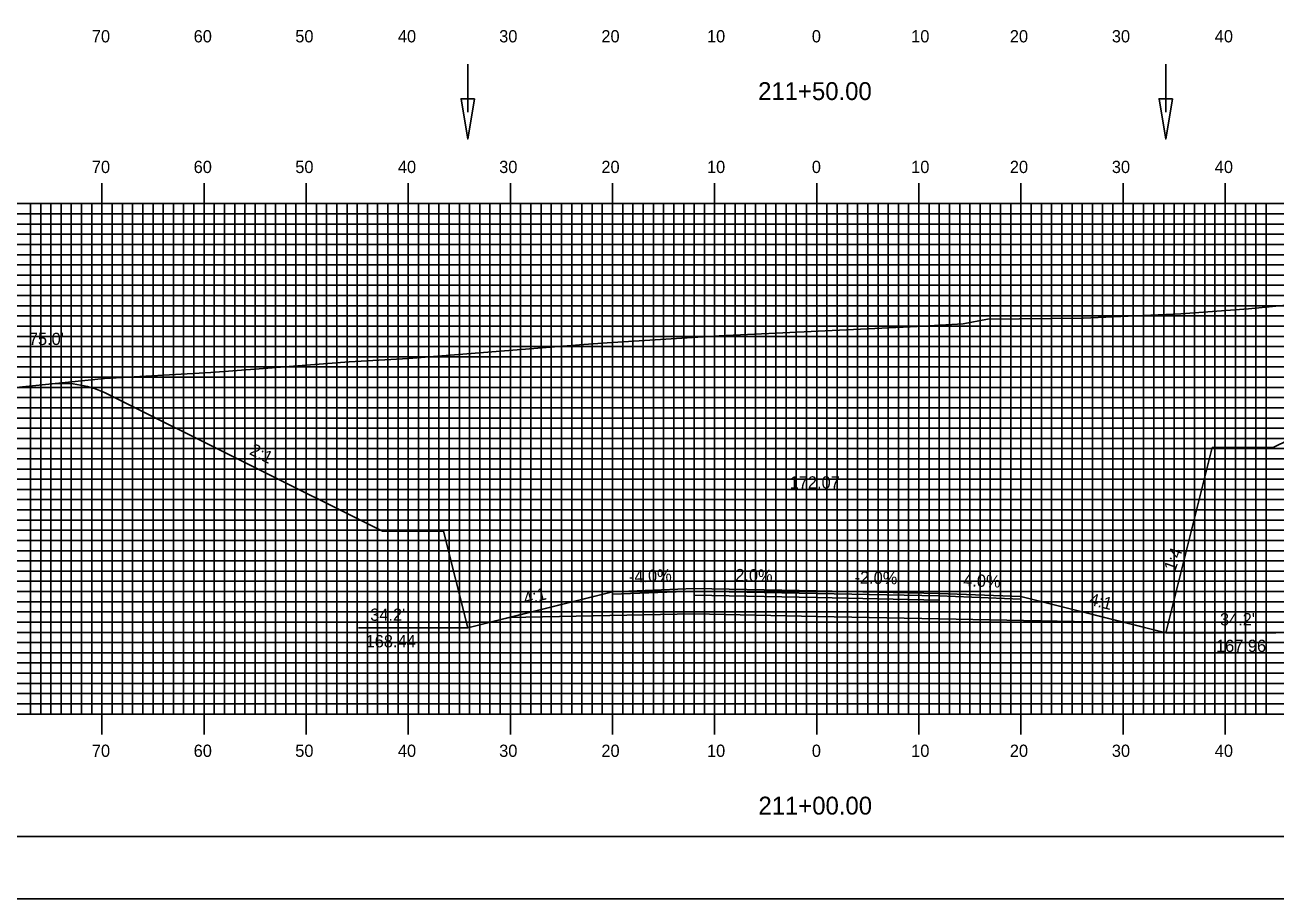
# Model space of a CAD drawing. Extents: x 1794846 to 1795189, y 442591 to 442811.
# Drawn here: x 1794934.3 to 1795056.8, y 442590.5 to 442676.2 of the extents above; entities that cross this region are included whole.
import ezdxf

# ---------------------------------------------------------------- set-up
doc = ezdxf.new("R2010")
doc.units = 0
for name, color, linetype in [('ANNOTATION', 7, 'Continuous'), ('BORDER', 7, 'Continuous'), ('D_Drainage_Ditch_Line', 7, 'Continuous'), ('D_Roadway_Centerline', 7, 'Continuous'), ('D_Roadway_Centerline_Text', 7, 'Continuous'), ('D_Roadway_Edge_Shoulder', 7, 'Continuous'), ('D_Roadway_Edge_TW', 7, 'Continuous'), ('D_Roadway_FinishedGrade', 7, 'Continuous'), ('D_Roadway_Pavement', 7, 'Continuous'), ('D_Roadway_SlopeLines', 7, 'Continuous'), ('D_Roadway_SubGrade', 7, 'Continuous'), ('D_Text_Standard', 7, 'Continuous'), ('H_V ANNOTATION', 7, 'Continuous'), ('MAJOR', 7, 'Continuous'), ('MINOR', 7, 'Continuous'), ('PDRAIN', 7, 'Continuous'), ('PLOT BOUNDARY', 7, 'Continuous'), ('S_Roadway_Centerline', 7, 'Continuous')]:
    doc.layers.add(name, color=color, linetype=linetype)

msp = doc.modelspace()

# ---------------------------------------------------------------- linework, layer by layer
at = {"layer": 'BORDER'}
msp.add_lwpolyline([(1794862.25, 442596.67), (1795182.25, 442596.67), (1795182.25, 442806.67), (1794862.25, 442806.67)], close=True, dxfattribs=at)
at = {"layer": 'D_Drainage_Ditch_Line'}
for p, q in [((1794977.68, 442667.63), (1794977.68, 442672.33)), ((1795046.03, 442667.63), (1795046.03, 442672.33))]:
    msp.add_line(p, q, dxfattribs=at)
for points in [[(1794978.34, 442668.94), (1794977.02, 442668.94), (1794977.68, 442665)], [(1795046.68, 442668.94), (1795045.37, 442668.94), (1795046.03, 442665)]]:
    msp.add_lwpolyline(points, close=True, dxfattribs=at)
at = {"layer": 'D_Roadway_Centerline'}
msp.add_lwpolyline([(1794977.68, 442617.11), (1794981.68, 442618.11), (1794991.85, 442620.65), (1794999.85, 442620.97), (1795011.85, 442620.73), (1795023.85, 442620.49), (1795031.85, 442620.17), (1795042.03, 442617.63), (1795046.03, 442616.63)], dxfattribs=at)
at = {"layer": 'D_Roadway_Edge_Shoulder'}
for points in [[(1794999.85, 442620.97), (1794991.85, 442620.65), (1794991.85, 442620.4), (1794999.85, 442620.72)], [(1795023.85, 442620.49), (1795031.85, 442620.17), (1795031.85, 442619.92), (1795023.85, 442620.24)]]:
    msp.add_lwpolyline(points, close=True, dxfattribs=at)
at = {"layer": 'D_Roadway_Edge_TW'}
msp.add_lwpolyline([(1794999.85, 442620.72), (1794999.85, 442620.97), (1795011.85, 442620.73), (1795023.85, 442620.49), (1795023.85, 442620.24), (1795011.85, 442620.48)], close=True, dxfattribs=at)
at = {"layer": 'D_Roadway_FinishedGrade'}
msp.add_arc((1794937.96, 442631.06), 10, 63.4349, 96.0931, dxfattribs=at)
at = {"layer": 'D_Roadway_Pavement'}
msp.add_lwpolyline([(1794999.85, 442620.31), (1794999.85, 442620.72), (1795011.85, 442620.48), (1795023.85, 442620.24), (1795023.85, 442619.83), (1795011.85, 442620.07)], close=True, dxfattribs=at)
at = {"layer": 'D_Roadway_SlopeLines'}
for p, q in [((1795056.56, 442634.77), (1795080.92, 442646.94)), ((1795046.03, 442616.63), (1795050.56, 442634.77)), ((1795050.56, 442634.77), (1795056.56, 442634.77)), ((1794977.68, 442617.11), (1794975.31, 442626.57))]:
    msp.add_line(p, q, dxfattribs=at)
for points in [[(1794975.31, 442626.57), (1794969.31, 442626.57), (1794942.43, 442640.01)], [(1794991.85, 442620.65), (1794977.68, 442617.11)], [(1795031.85, 442620.17), (1795046.03, 442616.63)]]:
    msp.add_lwpolyline(points, dxfattribs=at)
at = {"layer": 'D_Roadway_SubGrade'}
msp.add_lwpolyline([(1794999.85, 442618.47), (1794981.68, 442618.11), (1794991.85, 442620.65), (1794991.85, 442620.4), (1794999.85, 442620.72), (1795011.85, 442620.48), (1795023.85, 442620.24), (1795031.85, 442619.92), (1795031.85, 442620.17), (1795042.03, 442617.63), (1795023.85, 442617.99), (1795011.85, 442618.23)], close=True, dxfattribs=at)
at = {"layer": 'MAJOR'}
for p, q in [((1794941.85, 442660.67), (1794941.85, 442658.67)), ((1794951.85, 442660.67), (1794951.85, 442658.67)), ((1794961.85, 442660.67), (1794961.85, 442658.67)), ((1794971.85, 442660.67), (1794971.85, 442658.67)), ((1794981.85, 442660.67), (1794981.85, 442658.67)), ((1794991.85, 442660.67), (1794991.85, 442658.67)), ((1795001.85, 442660.67), (1795001.85, 442658.67)), ((1795011.85, 442660.67), (1795011.85, 442658.67)), ((1795021.85, 442660.67), (1795021.85, 442658.67)), ((1795031.85, 442660.67), (1795031.85, 442658.67)), ((1795041.85, 442660.67), (1795041.85, 442658.67)), ((1795051.85, 442660.67), (1795051.85, 442658.67)), ((1794871.85, 442658.67), (1795151.85, 442658.67)), ((1794871.85, 442658.67), (1795151.85, 442658.67)), ((1794941.85, 442608.67), (1794941.85, 442658.67)), ((1794951.85, 442608.67), (1794951.85, 442658.67)), ((1794961.85, 442608.67), (1794961.85, 442658.67)), ((1794971.85, 442608.67), (1794971.85, 442658.67)), ((1794981.85, 442608.67), (1794981.85, 442658.67)), ((1794991.85, 442608.67), (1794991.85, 442658.67)), ((1795001.85, 442608.67), (1795001.85, 442658.67)), ((1795011.85, 442608.67), (1795011.85, 442658.67)), ((1795021.85, 442608.67), (1795021.85, 442658.67)), ((1795031.85, 442608.67), (1795031.85, 442658.67)), ((1795041.85, 442608.67), (1795041.85, 442658.67)), ((1795051.85, 442608.67), (1795051.85, 442658.67)), ((1794871.85, 442653.67), (1795151.85, 442653.67)), ((1794871.85, 442648.67), (1795151.85, 442648.67)), ((1794871.85, 442643.67), (1795151.85, 442643.67)), ((1794871.85, 442638.67), (1795151.85, 442638.67)), ((1794871.85, 442633.67), (1795151.85, 442633.67)), ((1794871.85, 442628.67), (1795151.85, 442628.67)), ((1794871.85, 442623.67), (1795151.85, 442623.67)), ((1794871.85, 442618.67), (1795151.85, 442618.67)), ((1794871.85, 442613.67), (1795151.85, 442613.67)), ((1794871.85, 442608.67), (1795151.85, 442608.67)), ((1794871.85, 442608.67), (1795151.85, 442608.67)), ((1794941.85, 442606.66), (1794941.85, 442608.67)), ((1794951.85, 442606.66), (1794951.85, 442608.67)), ((1794961.85, 442606.66), (1794961.85, 442608.67)), ((1794971.85, 442606.66), (1794971.85, 442608.67)), ((1794981.85, 442606.66), (1794981.85, 442608.67)), ((1794991.85, 442606.66), (1794991.85, 442608.67)), ((1795001.85, 442606.66), (1795001.85, 442608.67)), ((1795011.85, 442606.66), (1795011.85, 442608.67)), ((1795021.85, 442606.66), (1795021.85, 442608.67)), ((1795031.85, 442606.66), (1795031.85, 442608.67)), ((1795041.85, 442606.66), (1795041.85, 442608.67)), ((1795051.85, 442606.66), (1795051.85, 442608.67))]:
    msp.add_line(p, q, dxfattribs=at)
at = {"layer": 'MINOR'}
for p, q in [((1794871.85, 442657.67), (1795151.85, 442657.67)), ((1794934.85, 442608.67), (1794934.85, 442658.67)), ((1794935.85, 442608.67), (1794935.85, 442658.67)), ((1794936.85, 442608.67), (1794936.85, 442658.67)), ((1794937.85, 442608.67), (1794937.85, 442658.67)), ((1794938.85, 442608.67), (1794938.85, 442658.67)), ((1794939.85, 442608.67), (1794939.85, 442658.67)), ((1794940.85, 442608.67), (1794940.85, 442658.67)), ((1794942.85, 442608.67), (1794942.85, 442658.67)), ((1794943.85, 442608.67), (1794943.85, 442658.67)), ((1794944.85, 442608.67), (1794944.85, 442658.67)), ((1794945.85, 442608.67), (1794945.85, 442658.67)), ((1794946.85, 442608.67), (1794946.85, 442658.67)), ((1794947.85, 442608.67), (1794947.85, 442658.67)), ((1794948.85, 442608.67), (1794948.85, 442658.67)), ((1794949.85, 442608.67), (1794949.85, 442658.67)), ((1794950.85, 442608.67), (1794950.85, 442658.67)), ((1794952.85, 442608.67), (1794952.85, 442658.67)), ((1794953.85, 442608.67), (1794953.85, 442658.67)), ((1794954.85, 442608.67), (1794954.85, 442658.67)), ((1794955.85, 442608.67), (1794955.85, 442658.67)), ((1794956.85, 442608.67), (1794956.85, 442658.67)), ((1794957.85, 442608.67), (1794957.85, 442658.67)), ((1794958.85, 442608.67), (1794958.85, 442658.67)), ((1794959.85, 442608.67), (1794959.85, 442658.67)), ((1794960.85, 442608.67), (1794960.85, 442658.67)), ((1794962.85, 442608.67), (1794962.85, 442658.67)), ((1794963.85, 442608.67), (1794963.85, 442658.67)), ((1794964.85, 442608.67), (1794964.85, 442658.67)), ((1794965.85, 442608.67), (1794965.85, 442658.67)), ((1794966.85, 442608.67), (1794966.85, 442658.67)), ((1794967.85, 442608.67), (1794967.85, 442658.67)), ((1794968.85, 442608.67), (1794968.85, 442658.67)), ((1794969.85, 442608.67), (1794969.85, 442658.67)), ((1794970.85, 442608.67), (1794970.85, 442658.67)), ((1794972.85, 442608.67), (1794972.85, 442658.67)), ((1794973.85, 442608.67), (1794973.85, 442658.67)), ((1794974.85, 442608.67), (1794974.85, 442658.67)), ((1794975.85, 442608.67), (1794975.85, 442658.67)), ((1794976.85, 442608.67), (1794976.85, 442658.67)), ((1794977.85, 442608.67), (1794977.85, 442658.67)), ((1794978.85, 442608.67), (1794978.85, 442658.67)), ((1794979.85, 442608.67), (1794979.85, 442658.67)), ((1794980.85, 442608.67), (1794980.85, 442658.67)), ((1794982.85, 442608.67), (1794982.85, 442658.67)), ((1794983.85, 442608.67), (1794983.85, 442658.67)), ((1794984.85, 442608.67), (1794984.85, 442658.67)), ((1794985.85, 442608.67), (1794985.85, 442658.67)), ((1794986.85, 442608.67), (1794986.85, 442658.67)), ((1794987.85, 442608.67), (1794987.85, 442658.67)), ((1794988.85, 442608.67), (1794988.85, 442658.67)), ((1794989.85, 442608.67), (1794989.85, 442658.67)), ((1794990.85, 442608.67), (1794990.85, 442658.67)), ((1794992.85, 442608.67), (1794992.85, 442658.67)), ((1794993.85, 442608.67), (1794993.85, 442658.67)), ((1794994.85, 442608.67), (1794994.85, 442658.67)), ((1794995.85, 442608.67), (1794995.85, 442658.67)), ((1794996.85, 442608.67), (1794996.85, 442658.67)), ((1794997.85, 442608.67), (1794997.85, 442658.67)), ((1794998.85, 442608.67), (1794998.85, 442658.67)), ((1794999.85, 442608.67), (1794999.85, 442658.67)), ((1795000.85, 442608.67), (1795000.85, 442658.67)), ((1795002.85, 442608.67), (1795002.85, 442658.67)), ((1795003.85, 442608.67), (1795003.85, 442658.67)), ((1795004.85, 442608.67), (1795004.85, 442658.67)), ((1795005.85, 442608.67), (1795005.85, 442658.67)), ((1795006.85, 442608.67), (1795006.85, 442658.67)), ((1795007.85, 442608.67), (1795007.85, 442658.67)), ((1795008.85, 442608.67), (1795008.85, 442658.67)), ((1795009.85, 442608.67), (1795009.85, 442658.67)), ((1795010.85, 442608.67), (1795010.85, 442658.67)), ((1795012.85, 442608.67), (1795012.85, 442658.67)), ((1795013.85, 442608.67), (1795013.85, 442658.67)), ((1795014.85, 442608.67), (1795014.85, 442658.67)), ((1795015.85, 442608.67), (1795015.85, 442658.67)), ((1795016.85, 442608.67), (1795016.85, 442658.67)), ((1795017.85, 442608.67), (1795017.85, 442658.67)), ((1795018.85, 442608.67), (1795018.85, 442658.67)), ((1795019.85, 442608.67), (1795019.85, 442658.67)), ((1795020.85, 442608.67), (1795020.85, 442658.67)), ((1795022.85, 442608.67), (1795022.85, 442658.67)), ((1795023.85, 442608.67), (1795023.85, 442658.67)), ((1795024.85, 442608.67), (1795024.85, 442658.67)), ((1795025.85, 442608.67), (1795025.85, 442658.67)), ((1795026.85, 442608.67), (1795026.85, 442658.67)), ((1795027.85, 442608.67), (1795027.85, 442658.67)), ((1795028.85, 442608.67), (1795028.85, 442658.67)), ((1795029.85, 442608.67), (1795029.85, 442658.67)), ((1795030.85, 442608.67), (1795030.85, 442658.67)), ((1795032.85, 442608.67), (1795032.85, 442658.67)), ((1795033.85, 442608.67), (1795033.85, 442658.67)), ((1795034.85, 442608.67), (1795034.85, 442658.67)), ((1795035.85, 442608.67), (1795035.85, 442658.67)), ((1795036.85, 442608.67), (1795036.85, 442658.67)), ((1795037.85, 442608.67), (1795037.85, 442658.67)), ((1795038.85, 442608.67), (1795038.85, 442658.67)), ((1795039.85, 442608.67), (1795039.85, 442658.67)), ((1795040.85, 442608.67), (1795040.85, 442658.67)), ((1795042.85, 442608.67), (1795042.85, 442658.67)), ((1795043.85, 442608.67), (1795043.85, 442658.67)), ((1795044.85, 442608.67), (1795044.85, 442658.67)), ((1795045.85, 442608.67), (1795045.85, 442658.67)), ((1795046.85, 442608.67), (1795046.85, 442658.67)), ((1795047.85, 442608.67), (1795047.85, 442658.67)), ((1795048.85, 442608.67), (1795048.85, 442658.67)), ((1795049.85, 442608.67), (1795049.85, 442658.67)), ((1795050.85, 442608.67), (1795050.85, 442658.67)), ((1795052.85, 442608.67), (1795052.85, 442658.67)), ((1795053.85, 442608.67), (1795053.85, 442658.67)), ((1795054.85, 442608.67), (1795054.85, 442658.67)), ((1795055.85, 442608.67), (1795055.85, 442658.67)), ((1794871.85, 442656.67), (1795151.85, 442656.67)), ((1794871.85, 442655.67), (1795151.85, 442655.67)), ((1794871.85, 442654.67), (1795151.85, 442654.67)), ((1794871.85, 442652.67), (1795151.85, 442652.67)), ((1794871.85, 442651.67), (1795151.85, 442651.67)), ((1794871.85, 442650.67), (1795151.85, 442650.67)), ((1794871.85, 442649.67), (1795151.85, 442649.67)), ((1794871.85, 442647.67), (1795151.85, 442647.67)), ((1794871.85, 442646.67), (1795151.85, 442646.67)), ((1794871.85, 442645.67), (1795151.85, 442645.67)), ((1794871.85, 442644.67), (1795151.85, 442644.67)), ((1794871.85, 442642.67), (1795151.85, 442642.67)), ((1794871.85, 442641.67), (1795151.85, 442641.67)), ((1794871.85, 442640.67), (1795151.85, 442640.67)), ((1794871.85, 442639.67), (1795151.85, 442639.67)), ((1794871.85, 442637.67), (1795151.85, 442637.67)), ((1794871.85, 442636.67), (1795151.85, 442636.67)), ((1794871.85, 442635.67), (1795151.85, 442635.67)), ((1794871.85, 442634.67), (1795151.85, 442634.67)), ((1794871.85, 442632.67), (1795151.85, 442632.67)), ((1794871.85, 442631.67), (1795151.85, 442631.67)), ((1794871.85, 442630.67), (1795151.85, 442630.67)), ((1794871.85, 442629.67), (1795151.85, 442629.67)), ((1794871.85, 442627.67), (1795151.85, 442627.67)), ((1794871.85, 442626.67), (1795151.85, 442626.67)), ((1794871.85, 442625.67), (1795151.85, 442625.67)), ((1794871.85, 442624.67), (1795151.85, 442624.67)), ((1794871.85, 442622.67), (1795151.85, 442622.67)), ((1794871.85, 442621.67), (1795151.85, 442621.67)), ((1794871.85, 442620.67), (1795151.85, 442620.67)), ((1794871.85, 442619.67), (1795151.85, 442619.67)), ((1794871.85, 442617.67), (1795151.85, 442617.67)), ((1794871.85, 442616.67), (1795151.85, 442616.67)), ((1794871.85, 442615.67), (1795151.85, 442615.67)), ((1794871.85, 442614.67), (1795151.85, 442614.67)), ((1794871.85, 442612.67), (1795151.85, 442612.67)), ((1794871.85, 442611.67), (1795151.85, 442611.67)), ((1794871.85, 442610.67), (1795151.85, 442610.67)), ((1794871.85, 442609.67), (1795151.85, 442609.67))]:
    msp.add_line(p, q, dxfattribs=at)
at = {"layer": 'PDRAIN'}
for p, q in [((1794966.96, 442617.11), (1794977.68, 442617.11)), ((1795046.03, 442616.63), (1795056.8, 442616.63))]:
    msp.add_line(p, q, dxfattribs=at)
at = {"layer": 'PLOT BOUNDARY'}
msp.add_lwpolyline([(1794846.07, 442590.55), (1795186.07, 442590.55), (1795186.07, 442810.55), (1794846.07, 442810.55)], close=True, dxfattribs=at)
at = {"layer": 'S_Roadway_Centerline'}
msp.add_lwpolyline([(1794933.11, 442640.62), (1794942.11, 442641.54), (1794952.51, 442642.12), (1794957.26, 442642.48), (1794966.05, 442643.17), (1794971.87, 442643.49), (1794989.03, 442644.86), (1794991.33, 442645.03), (1795002.28, 442645.72), (1795021.68, 442646.62), (1795026.19, 442646.89), (1795028.56, 442647.35), (1795037.95, 442647.46), (1795047.5, 442647.87), (1795054.13, 442648.38), (1795062.84, 442649.21)], dxfattribs=at)

# ---------------------------------------------------------------- texts
at = {"layer": 'ANNOTATION'}
for s, rotation, p in [('2:1', 333.4349, (1794956.21, 442634.15)), ('2:1', 333.4349, (1794956.21, 442634.15)), ('1:4', 70.516, (1795046.94, 442622.58)), ('1:4', 70.516, (1795046.94, 442622.58)), ('-4.0%', 2.2906, (1794993.48, 442621.52)), ('2.0%', 358.8542, (1795003.86, 442621.69)), ('-2.0%', 358.8542, (1795015.54, 442621.46)), ('-4.0%', 357.7094, (1795025.64, 442621.22)), ('4:1', 14.0362, (1794983.3, 442619.38)), ('4:1', 345.9638, (1795038.45, 442619.39))]:
    msp.add_text(s, height=1.2, rotation=rotation, dxfattribs=at).set_placement(p)
for s, p in [("34.2'", (1794968.12, 442617.8)), ("34.2'", (1795051.34, 442617.35)), ('168.44', (1794967.67, 442615.2)), ('167.96', (1795050.95, 442614.75))]:
    msp.add_text(s, height=1.2, dxfattribs=at).set_placement(p)
at = {"layer": 'D_Roadway_Centerline'}
for s, p in [('C', (1795011.85, 442620.73)), ('L', (1795011.85, 442620.72))]:
    msp.add_text(s, height=0.0146, dxfattribs=at).set_placement(p)
at = {"layer": 'D_Roadway_Centerline_Text'}
msp.add_text('172.07', height=1.2, dxfattribs=at).set_placement((1795009.2, 442630.76))
at = {"layer": 'D_Text_Standard'}
msp.add_text("75.0'", height=1.2, dxfattribs=at).set_placement((1794934.69, 442644.82))
at = {"layer": 'H_V ANNOTATION'}
for s, height, p in [('70', 1.2, (1794940.86, 442674.47)), ('60', 1.2, (1794950.83, 442674.47)), ('50', 1.2, (1794960.78, 442674.47)), ('40', 1.2, (1794970.83, 442674.47)), ('30', 1.2, (1794980.75, 442674.47)), ('20', 1.2, (1794990.76, 442674.47)), ('10', 1.2, (1795001.1, 442674.47)), ('0', 1.2, (1795011.37, 442674.47)), ('10', 1.2, (1795021.1, 442674.47)), ('20', 1.2, (1795030.76, 442674.47)), ('30', 1.2, (1795040.75, 442674.47)), ('40', 1.2, (1795050.83, 442674.47)), ('211+50.00', 1.75, (1795006.11, 442668.82)), ('70', 1.2, (1794940.86, 442661.67)), ('60', 1.2, (1794950.83, 442661.67)), ('50', 1.2, (1794960.78, 442661.67)), ('40', 1.2, (1794970.83, 442661.67)), ('30', 1.2, (1794980.75, 442661.67)), ('20', 1.2, (1794990.76, 442661.67)), ('10', 1.2, (1795001.1, 442661.67)), ('0', 1.2, (1795011.37, 442661.67)), ('10', 1.2, (1795021.1, 442661.67)), ('20', 1.2, (1795030.76, 442661.67)), ('30', 1.2, (1795040.75, 442661.67)), ('40', 1.2, (1795050.83, 442661.67)), ('70', 1.2, (1794940.86, 442604.47)), ('60', 1.2, (1794950.83, 442604.47)), ('50', 1.2, (1794960.78, 442604.47)), ('40', 1.2, (1794970.83, 442604.47)), ('30', 1.2, (1794980.75, 442604.47)), ('20', 1.2, (1794990.76, 442604.47)), ('10', 1.2, (1795001.1, 442604.47)), ('0', 1.2, (1795011.37, 442604.47)), ('10', 1.2, (1795021.1, 442604.47)), ('20', 1.2, (1795030.76, 442604.47)), ('30', 1.2, (1795040.75, 442604.47)), ('40', 1.2, (1795050.83, 442604.47)), ('211+00.00', 1.75, (1795006.14, 442598.82))]:
    msp.add_text(s, height=height, dxfattribs=at).set_placement(p)

doc.saveas('drawing.dxf')
